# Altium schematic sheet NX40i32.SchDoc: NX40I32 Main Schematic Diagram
size A3; DocumentNumber: 2; SheetNumber: 2; SheetTotal: 2
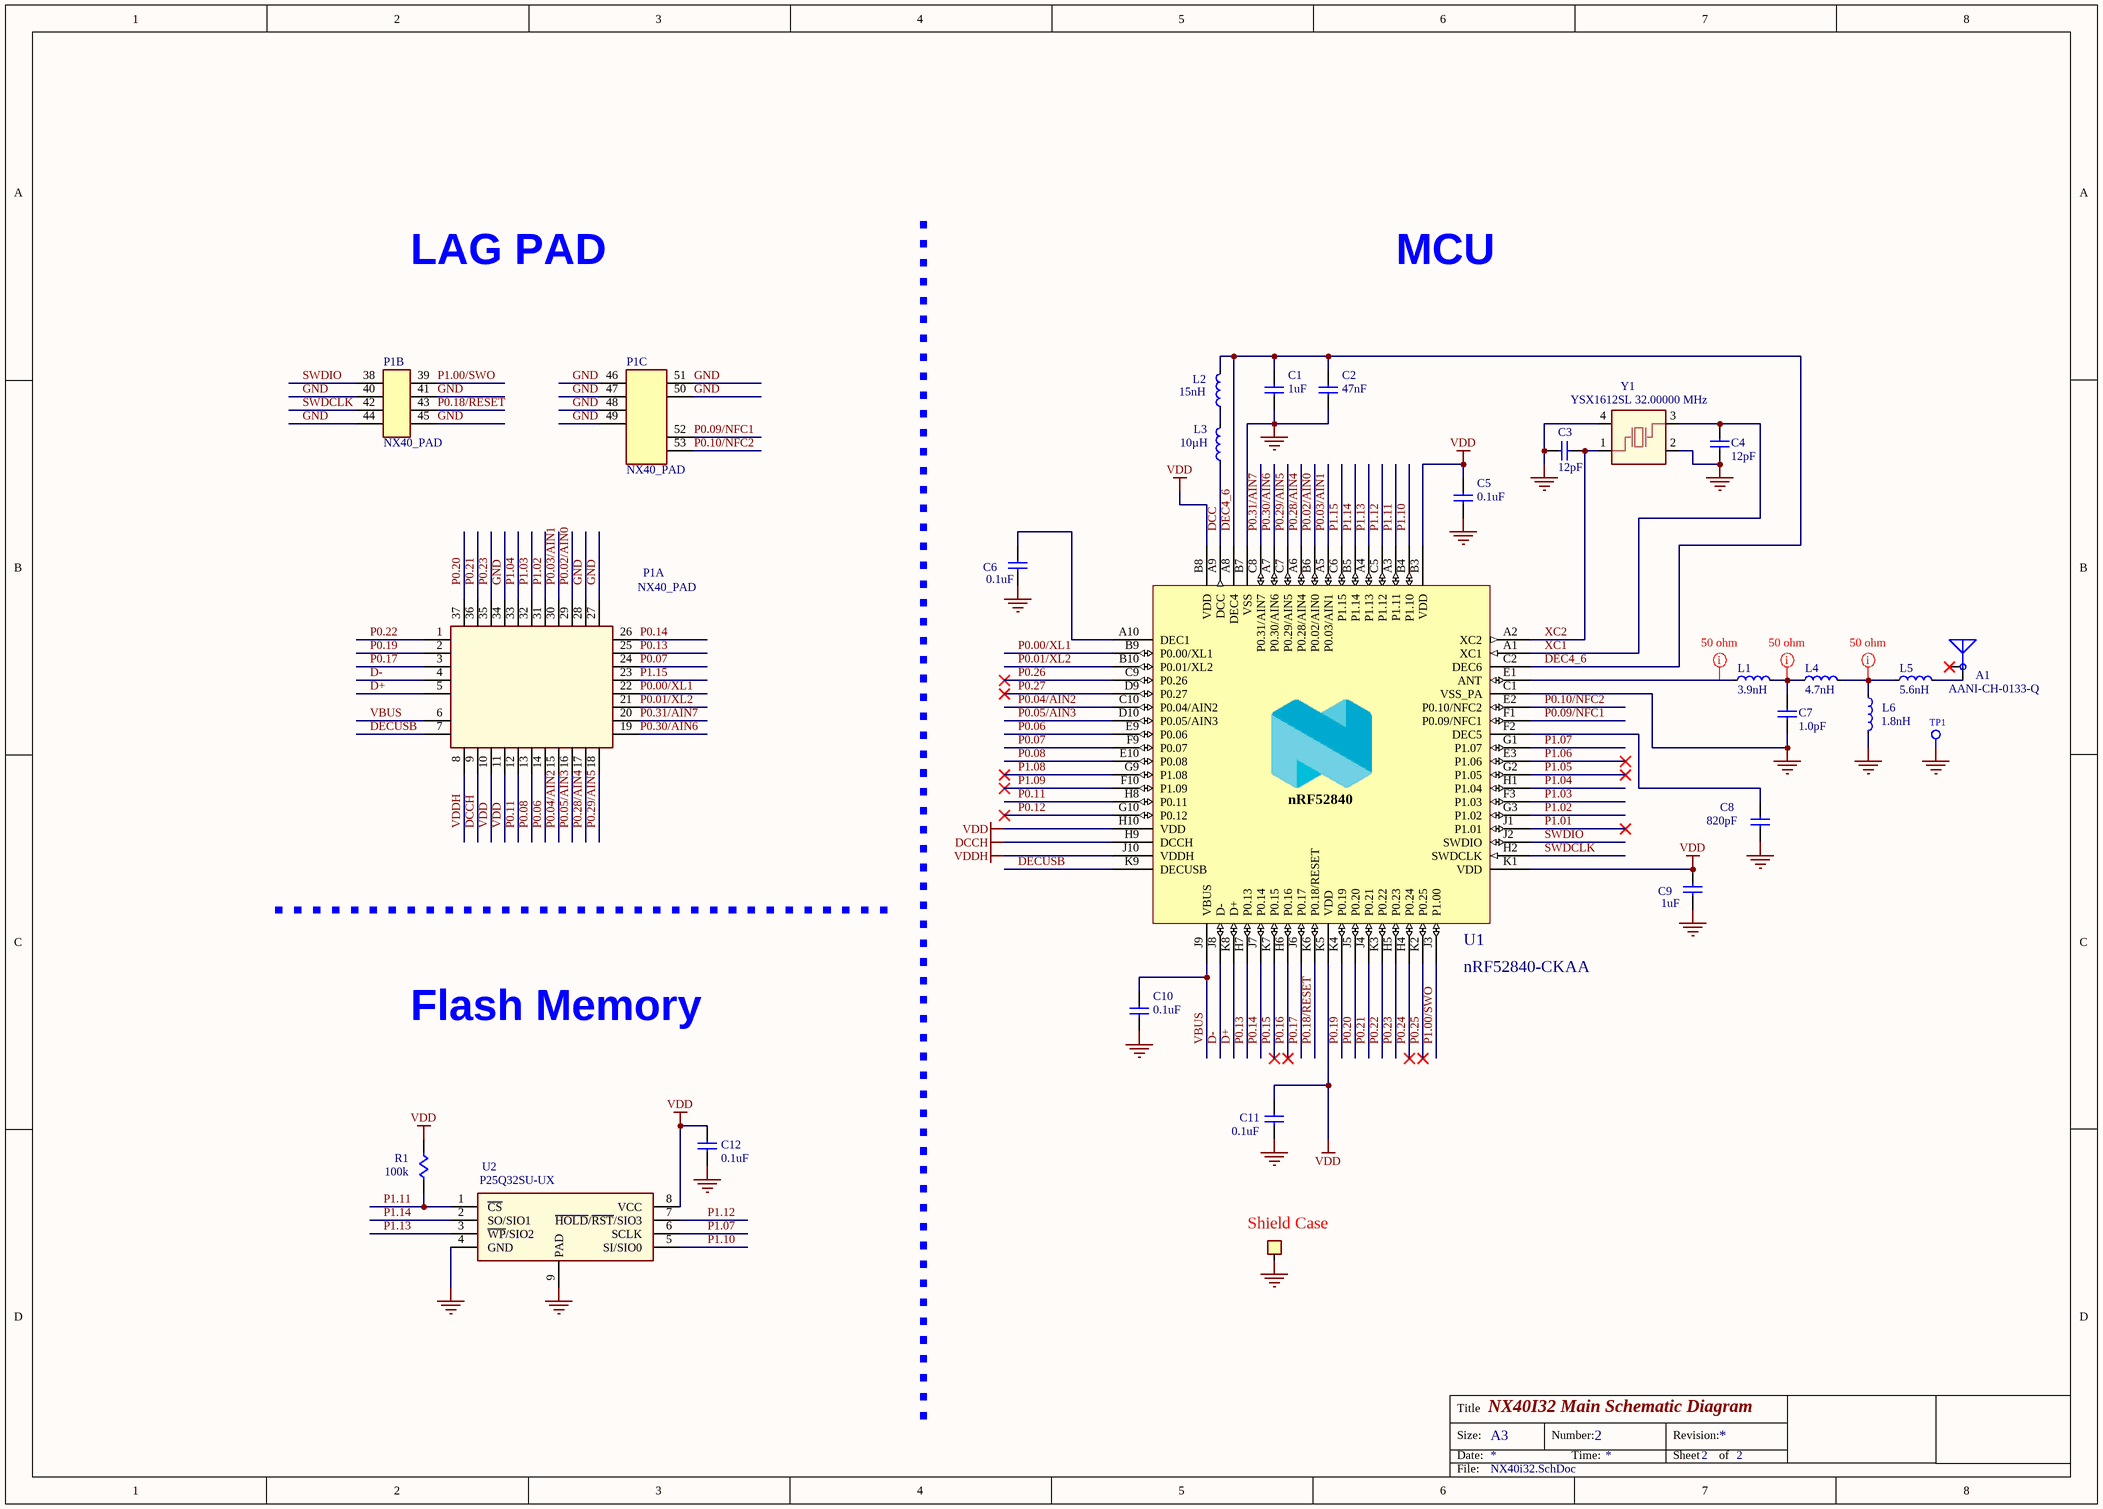
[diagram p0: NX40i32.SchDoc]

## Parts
A1  AANI-CH-0133-Q  [ANT AANI-CH-0133-Q]
C1  1uF  [CAP 0201/0603X03L_NX]
C2  47nF  [CAP 0201/0603X03L_NX]
C3  12pF  [CAP 0201/0603X03L_NX]
C4  12pF  [CAP 0201/0603X03L_NX]
C5  0.1uF  [CAP 0201/0603X03L_NX]
C6  0.1uF  [CAP 0201/0603X03L_NX]
C7  1.0pF  [CAP 0201/0603X03L_NX]
C8  820pF  [CAP 0201/0603X03L_NX]
C9  1uF  [CAP 0201/0603X03L_NX]
C10  0.1uF  [CAP 0201/0603X03L_NX]
C11  0.1uF  [CAP 0201/0603X03L_NX]
C12  0.1uF  [CAP 0201/0603X03L_NX]
L1  3.9nH  [IND 0201/0603X03L_NX]
L2  15nH  [IND 0402/1005_NX]
L3  10µH  [IND 0603/1608X08L_NX]
L4  4.7nH  [IND 0201/0603X03L_NX]
L5  5.6nH  [IND 0201/0603X03L_NX]
L6  1.8nH  [IND 0201/0603X03L_NX]
P1  NX40_PAD  [NX40_PAD]  (parts A,B,C of 3)
R1  100k  [RES 0201/0603]
T?  SHILED CASE  [Shield_can_Korlinx]  (value not drawn)  (no BOM)
TP1  5010  [TP / 0.3]  (value not drawn)  (no BOM)
U1  nRF52840-CKAA  [BGA94C35P10X10_352X356X50]
U2  P25Q32SU-UX  [USON-8 2X3 /PSON50P300X200X60-9N]
Y1  YSX1612SL 32.00000 MHz  [XTAL/1612]

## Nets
DCCH: P1.9 U1.H9(DCCH)
GND: C1.1 C2.2 C3.1 C4.2 C5.2 C6.2 C7.1 C8.1 C9.2 C10.2 C11.1 C12.1 L6.2 P1.27 P1.28 P1.34 P1.40 P1.41 P1.44 P1.45 P1.46 P1.47 P1.48 P1.49 P1.50 P1.51 T?.1 TP1.1 U1.B7(VSS) U1.C1(VSS_PA) U1.C4(GND) U1.D3(GND) U1.D4(GND) U1.D5(GND) U1.D6(GND) U1.D7(GND) U1.D8(GND) U1.E4(GND) U1.E5(GND) U1.E6(GND) U1.E7(GND) U1.E8(GND) U1.F4(GND) U1.F5(GND) U1.F6(GND) U1.F7(GND) U1.F8(GND) U1.G4(GND) U1.G5(GND) U1.G6(GND) U1.G7(GND) U1.G8(GND) U1.K10(GND) U2.4(GND) U2.9(PAD) Y1.2(GND) Y1.4(GND)
VDD: C5.1 C9.1 C11.2 C12.2 P1.10 P1.11 R1.2 U1.B3(VDD) U1.B8(VDD) U1.H10(VDD) U1.K1(VDD) U1.K5(VDD) U2.8(VCC)
VDDH: P1.8 U1.J10(VDDH)
D+: P1.5 U1.K8(D+)
D-: P1.4 U1.J8(D-)
DCC: L3.1 U1.A9(DCC)
DEC4_6: C1.2 C2.1 L2.2 U1.A8(DEC4) U1.C2(DEC6)
DECUSB: P1.7 U1.K9(DECUSB)
P0.00/XL1: P1.22 U1.B9(P0.00/XL1)
P0.01/XL2: P1.21 U1.B10(P0.01/XL2)
P0.02/AIN0: P1.29 U1.B6(P0.02/AIN0)
P0.03/AIN1: P1.30 U1.A5(P0.03/AIN1)
P0.04/AIN2: P1.15 U1.C10(P0.04/AIN2)
P0.05/AIN3: P1.16 U1.D10(P0.05/AIN3)
P0.06: P1.14 U1.E9(P0.06)
P0.07: P1.24 U1.F9(P0.07)
P0.08: P1.13 U1.E10(P0.08)
P0.09/NFC1: P1.52 U1.F1(P0.09/NFC1)
P0.10/NFC2: P1.53 U1.E2(P0.10/NFC2)
P0.11: P1.12 U1.H8(P0.11)
P0.12: U1.G10(P0.12)
P0.13: P1.25 U1.H7(P0.13)
P0.14: P1.26 U1.J7(P0.14)
P0.15: U1.K7(P0.15)
P0.16: U1.H6(P0.16)
P0.17: P1.3 U1.J6(P0.17)
P0.18/RESET: P1.43 U1.K6(P0.18/RESET)
P0.19: P1.2 U1.K4(P0.19)
P0.20: P1.37 U1.J5(P0.20)
P0.21: P1.36 U1.J4(P0.21)
P0.22: P1.1 U1.K3(P0.22)
P0.23: P1.35 U1.H5(P0.23)
P0.24: U1.H4(P0.24)
P0.25: U1.K2(P0.25)
P0.26: U1.C9(P0.26)
P0.27: U1.D9(P0.27)
P0.28/AIN4: P1.17 U1.A6(P0.28/AIN4)
P0.29/AIN5: P1.18 U1.C7(P0.29/AIN5)
P0.30/AIN6: P1.19 U1.A7(P0.30/AIN6)
P0.31/AIN7: P1.20 U1.C8(P0.31/AIN7)
P1.00/SWO: P1.39 U1.J3(P1.00)
P1.01: U1.J1(P1.01)
P1.02: P1.31 U1.G3(P1.02)
P1.03: P1.32 U1.F3(P1.03)
P1.04: P1.33 U1.H1(P1.04)
P1.05: U1.G2(P1.05)
P1.06: U1.E3(P1.06)
P1.07: U1.G1(P1.07) U2.6(SCLK)
P1.08: U1.G9(P1.08)
P1.09: U1.F10(P1.09)
P1.10: U1.B4(P1.10) U2.5(SI/SIO0)
P1.11: R1.1 U1.A3(P1.11) U2.1(~{CS})
P1.12: U1.C5(P1.12) U2.7(~{HOLD}/~{RST}/SIO3)
P1.13: U1.A4(P1.13) U2.3(~{WP}/SIO2)
P1.14: U1.B5(P1.14) U2.2(SO/SIO1)
P1.15: P1.23 U1.C6(P1.15)
SWDCLK: P1.42 U1.H2(SWDCLK)
SWDIO: P1.38 U1.J2(SWDIO)
VBUS: C10.1 P1.6 U1.J9(VBUS)
XC1: C4.1 U1.A1(XC1) Y1.3(OSC2)
XC2: C3.2 U1.A2(XC2) Y1.1(OSC1)
NetA1_1: A1.1 L5.2
NetC6_1: C6.1 U1.A10(DEC1)
NetC7_2: C7.2 L1.2 L4.1
NetC8_2: C8.2 U1.F2(DEC5)
NetL1_1: L1.1 U1.E1(ANT)
NetL2_1: L2.1 L3.2
NetL4_2: L4.2 L5.1 L6.1

Not connected (* = marked no-connect by the designer): A1 2*

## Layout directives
net class 50s; rule Width Constraint [Pref Width = 6.2mil    Min Width = 6.2mil    Max Width = 6.2mil]: NetC7_2, NetL1_1, NetL4_2

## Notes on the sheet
- LAG PAD
- MCU
- Flash Memory
- (near T?) Shield Case

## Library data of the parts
A1 = ANT
C1 = C0201-10n: Capacitor, X5R, ±10%; Part number IPS: 00000003480; Note: 10V; Artikkelnr Noca: N.A.
C2 C6 C9 C10 = C0603-4µ7-6.3V-X7R: Capacitor, X5R, ±10%
C3 C4 = C0402-12p: Capacitor, NP0, ±2%; Manufacturer: N.A.; Part number IPS: 00000002398; Note: 50V; Artikkelnr Noca: 20029159; Pad Count: 2
C5 = C0603-4µ7-6.3V-X7R: Capacitor, X7R, ±10%
C7 C8 C12 = C0402-100p: Capacitor, NP0, ±5%; Manufacturer: N.A.; Part number IPS: 00000002361; Note: 50V; Artikkelnr Noca: 20029135; Pad Count: 2
C11 = C0402-100p: Capacitor, X5R, ±10%; Manufacturer: N.A.; Part number IPS: 00000002361; Note: 50V; Artikkelnr Noca: 20029135; Pad Count: 2
L1 L2 L4-L6 = L0201-4n7: Inductor; Manufacturer: Murata; Manufacturer Part Number: LQP03TN4N7H02D; Part number IPS: 00000001792; Note: N.A.; Pad Count: 2
L3 = L0603-10µ: Chip inductor, IDC,min = 50 mA, ±20%
P1 = NX40_PAD: NX40 PAD
R1 = Res1: Resistor; Value: 1K
T? = PAD SQUARE
TP1 = TP: Test Point; Manufacturer: Keystone; CompType: Test Point Loop; ContactFinish: Silver
U1 = nRF52840-CKAA: Multi-protocol Bluetooth Low Energy, IEEE 802.15.4, ANT and 2.4GHz proprietary system-on-chip; Pad Count: 94
U2 = P25Q32SU
Y1 = OSC-4: BOM_Manufacturer: TKD; BOM_Manufacturer Part: SX32Y025000BC1T; nameAlias: Frequency; Contributor: LCSC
